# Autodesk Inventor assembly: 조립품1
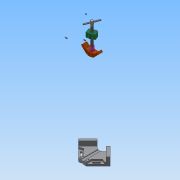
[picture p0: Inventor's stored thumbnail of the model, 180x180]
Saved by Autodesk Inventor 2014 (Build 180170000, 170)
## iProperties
Created: 2019-04
Part Number: 조립품1
Document SubType Name: Assembly
Designer: net
Author: net
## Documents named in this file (10)
- C:\Users\net\Desktop\490407V1035\답안조립품.iam
- C:\Users\net\Desktop\490407V1035\본체.ipt
- C:\Users\net\Desktop\490407V1035\멈춤나사 M4x5.ipt
- C:\Users\net\Desktop\490407V1035\멈춤나사 M4x10.ipt
- C:\Users\net\Desktop\490407V1035\평행 핀 2.5x24.ipt
- C:\Users\net\Desktop\490407V1035\핸들.ipt
- C:\Users\net\Desktop\490407V1035\조.ipt
- C:\Users\net\Desktop\490407V1035\리드스크류.ipt
- C:\Users\net\Desktop\490407V1035\부시.ipt
- C:\Users\net\Desktop\490407V1035\서포트.ipt
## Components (1 placed, 1 different names)
1. 핸들:1
